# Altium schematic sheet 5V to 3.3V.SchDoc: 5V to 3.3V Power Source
size Letter
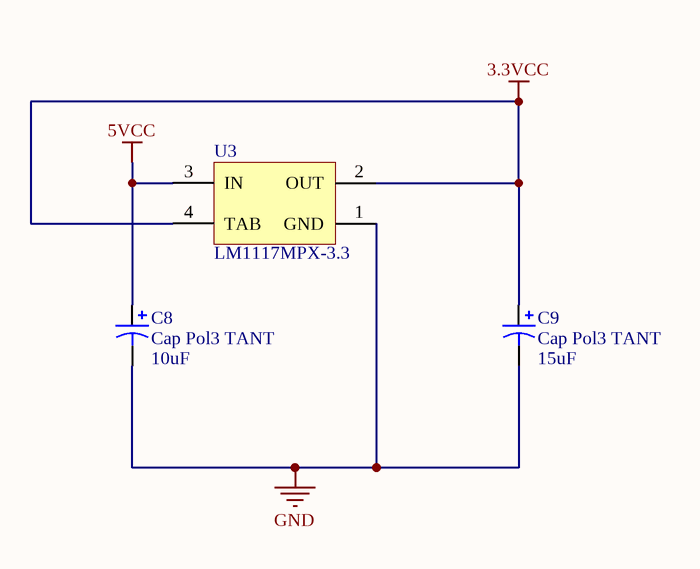
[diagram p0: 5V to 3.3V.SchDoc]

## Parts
C8  Cap Pol3 TANT  value 10uF  [CAPC3216N]
C9  Cap Pol3 TANT  value 15uF  [CAPC3216N]
U3  LM1117MPX-3.3  [MP04A_N]

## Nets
3.3VCC: C9.1 U3.2(OUT) U3.4(TAB)
5VCC: C8.1 U3.3(IN)
GND: C8.2 C9.2 U3.1(GND)

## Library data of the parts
C8 C9 = Cap Pol3: Polarized Capacitor (Surface Mount)
U3 = LM1117MPX-3.3: 800mA Low-Dropout Linear Regulator, 4-pin SOT-223; Manufacturer: National Semiconductor; PackageTopMarking: XYTT*N05A; PowerWise: N; CompType: LDO IC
